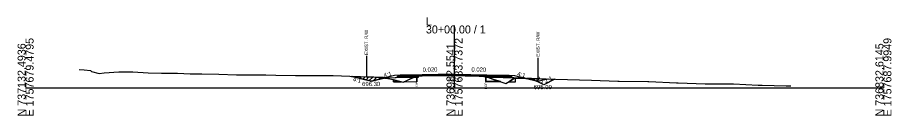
# Model space of a CAD drawing. Extents: x -26 to 4303, y -10 to 9577.
# Drawn here: x 1997.2 to 2302.8, y -9.7 to 24.7 of the extents above; entities that cross this region are included whole.
import ezdxf

# ---------------------------------------------------------------- set-up
doc = ezdxf.new("R2010")
doc.units = 0
for name, color, linetype in [('Default', 7, 'Continuous'), ('Exist CMT Pavement', 7, 'Continuous'), ('Old_Level_10', 7, 'Continuous'), ('Old_Level_2', 7, 'Continuous'), ('Pattern 1', 7, 'Continuous'), ('Prop CMT Conc Surface', 7, 'Continuous'), ('Prop CMT Concrete Structures', 7, 'Continuous'), ('Prop CMT Concrete Wall', 7, 'Continuous'), ('Prop CMT Pvmt Course 1', 7, 'Continuous'), ('Prop CMT Pvmt Course 1 CG', 7, 'Continuous'), ('Prop CMT Pvmt Course 1 Wedge', 7, 'Continuous'), ('Prop CMT Pvmt Course 2', 7, 'Continuous'), ('Prop CMT Pvmt Course 2 Wedge', 7, 'Continuous'), ('Prop CMT Pvmt Course 3', 7, 'Continuous'), ('Prop CMT Pvmt Surface', 7, 'Continuous'), ('Prop CMT Pvmt Surface Shoulder', 7, 'Continuous'), ('Prop CMT Pvmt Wedge Surface 1', 7, 'Continuous'), ('Prop CMT Pvmt Wedge Surface 2', 7, 'Continuous'), ('Prop CMT Pvmt Wedge Surface 3', 7, 'Continuous'), ('Prop CMT Shld Paved Course 1', 7, 'Continuous'), ('Prop CMT Shld Paved Course 2', 7, 'Continuous'), ('Prop CMT Shld Paved Course 3', 7, 'Continuous'), ('Prop CMT Slope Grass', 7, 'Continuous'), ('Prop CMT Subgrade Earthwork', 7, 'Continuous'), ('Prop Road Sect_ Recs - UC Shallow (Outline)', 7, 'Continuous'), ('Prop Shade Light', 7, 'Continuous'), ('Prop XS DDE Elevations', 7, 'Continuous'), ('Prop XS Ditch Standard Text', 7, 'Continuous'), ('Prop XS Earthwork Shape', 7, 'Continuous'), ('Prop XS Hydro Elevations', 7, 'Continuous'), ('Prop XS SE Text', 7, 'Continuous'), ('Prop XS Side Slope Text', 7, 'Continuous'), ('Prop XS Wedging', 7, 'Continuous')]:
    doc.layers.add(name, color=color, linetype=linetype)

msp = doc.modelspace()

# ---------------------------------------------------------------- linework, layer by layer
at = {"layer": 'Exist CMT Pavement'}
for points in [[(2150, 4.84), (2133, 4.5)], [(2150, 4.84), (2167, 4.5)]]:
    msp.add_lwpolyline(points, dxfattribs=at)
at = {"layer": 'Old_Level_10'}
for p, q in [((2176.98, 3.2), (2174.98, 3.3)), ((2181.21, 1.09), (2176.98, 3.2)), ((2185.05, 3.01), (2181.21, 1.09))]:
    msp.add_line(p, q, dxfattribs=at)
at = {"layer": 'Old_Level_2'}
for p, q in [((2150, 0), (2150, 21.86)), ((2150, 0), (2150, 21.86)), ((2000, 0), (2150, 0)), ((2150, 0), (2300, 0)), ((2000, 0), (2150, 0)), ((2150, 0), (2300, 0))]:
    msp.add_line(p, q, dxfattribs=at)
at = {"layer": 'Pattern 1'}
for p, q in [((2114.55, 3.95), (2114.62, 4.02)), ((2115.68, 3.67), (2115.98, 3.96)), ((2116.81, 3.38), (2117.34, 3.91)), ((2117.94, 3.1), (2118.7, 3.86)), ((2119.07, 2.82), (2120.07, 3.81)), ((2120.2, 2.53), (2121.44, 3.77)), ((2121.56, 2.47), (2122.8, 3.72)), ((2123.44, 2.95), (2124.17, 3.67)), ((2125.33, 3.42), (2125.48, 3.57)), ((2160.97, 3.82), (2161.11, 3.96)), ((2175.45, 3.22), (2175.51, 3.29)), ((2176.58, 2.94), (2176.88, 3.24)), ((2177.71, 2.66), (2178.25, 3.2)), ((2178.84, 2.37), (2179.63, 3.16)), ((2180.62, 2.74), (2181, 3.12))]:
    msp.add_line(p, q, dxfattribs=at)
for points in [[(2121, 2.34), (2125.73, 3.52), (2125.21, 3.64), (2121.77, 3.76), (2117.15, 3.92), (2114.21, 4.03)], [(2135.85, 3.72), (2136.77, 4.12), (2136.77, 3.74)], [(2161.61, 3.77), (2160.99, 4.01), (2160.97, 4.01), (2160.97, 3.78)], [(2179, 2.34), (2182.02, 3.09), (2179.71, 3.16), (2176.94, 3.24), (2175.16, 3.3)]]:
    msp.add_lwpolyline(points, close=True, dxfattribs=at)
at = {"layer": 'Prop CMT Conc Surface'}
for points in [[(2136.77, 4.32), (2133, 4.25)], [(2133, 4.25), (2133, 4.04)], [(2133, 4.04), (2136.77, 4.11)], [(2136.77, 4.11), (2136.77, 4.32)], [(2160.97, 4.16), (2160.97, 4.37)], [(2160.97, 4.37), (2167, 4.25)], [(2167, 4.04), (2160.97, 4.16)], [(2167, 4.25), (2167, 4.04)]]:
    msp.add_lwpolyline(points, dxfattribs=at)
at = {"layer": 'Prop CMT Concrete Structures'}
for points in [[(2133, 4.25), (2133, 4.5)], [(2136.77, 4.32), (2133, 4.25)], [(2150, 4.71), (2136.77, 4.45)], [(2136.77, 4.45), (2136.77, 4.32)], [(2150, 4.71), (2160.97, 4.49)], [(2160.97, 4.49), (2160.97, 4.37)], [(2160.97, 4.37), (2167, 4.25)], [(2167, 4.25), (2167, 4.5)]]:
    msp.add_lwpolyline(points, dxfattribs=at)
at = {"layer": 'Prop CMT Pvmt Course 1'}
for points in [[(2136.77, 4.11), (2133, 4.04)], [(2133, 4.04), (2133, 3.71)], [(2133, 3.71), (2136.77, 3.78)], [(2136.77, 3.78), (2136.77, 4.11)], [(2160.97, 4.16), (2167, 4.04)], [(2160.97, 3.83), (2160.97, 4.16)], [(2167, 3.71), (2160.97, 3.83)], [(2167, 4.04), (2167, 3.71)]]:
    msp.add_lwpolyline(points, dxfattribs=at)
at = {"layer": 'Prop CMT Pvmt Course 1 Wedge'}
for points in [[(2147.87, 4.33), (2148.83, 4.35)], [(2150, 4.3), (2149.18, 4.31), (2148.83, 4.32), (2147.87, 4.33)], [(2148.83, 4.35), (2149.18, 4.35), (2150, 4.37)], [(2150, 4.37), (2150, 4.3)], [(2150, 4.37), (2150.55, 4.36), (2150.86, 4.35), (2151.3, 4.34), (2151.3, 4.34), (2153.71, 4.3), (2153.81, 4.29), (2156.14, 4.25), (2156.31, 4.24), (2158.58, 4.2), (2158.81, 4.19), (2159.08, 4.19), (2159.99, 4.17), (2160.2, 4.17), (2160.29, 4.16), (2160.57, 4.16), (2160.61, 4.16), (2160.71, 4.16), (2160.97, 4.15)], [(2160.97, 4.01), (2160.71, 4.02), (2160.61, 4.03), (2160.57, 4.03), (2160.29, 4.04), (2160.2, 4.05), (2159.99, 4.06), (2159.08, 4.09), (2158.81, 4.1), (2158.58, 4.11), (2156.31, 4.17), (2156.14, 4.18), (2153.81, 4.27), (2153.71, 4.27), (2151.3, 4.31), (2151.3, 4.31), (2150.86, 4.3), (2150.55, 4.3), (2150, 4.3)], [(2160.97, 4.15), (2160.97, 4.01)]]:
    msp.add_lwpolyline(points, dxfattribs=at)
at = {"layer": 'Prop CMT Pvmt Course 2'}
for points in [[(2133, 4.5), (2131, 4.46), (2130.74, 4.2)], [(2130.74, 4.2), (2133, 4.25)], [(2133, 4.25), (2133, 4.5)], [(2167, 4.5), (2169, 4.46), (2169.26, 4.2)], [(2167, 4.25), (2167, 4.5)], [(2169.26, 4.2), (2167, 4.25)]]:
    msp.add_lwpolyline(points, dxfattribs=at)
at = {"layer": 'Prop CMT Pvmt Course 2 Wedge'}
for points in [[(2131, 4.46), (2129, 4.3), (2121, 2.3), (2114.02, 4.04)], [(2169, 4.46), (2171, 4.3), (2174.98, 3.3)]]:
    msp.add_lwpolyline(points, dxfattribs=at)
at = {"layer": 'Prop CMT Pvmt Course 3'}
for points in [[(2133, 4.25), (2130.74, 4.2), (2130.53, 3.99)], [(2130.53, 3.99), (2133, 4.04)], [(2133, 4.04), (2133, 4.25)], [(2167, 4.25), (2169.26, 4.2), (2169.47, 3.99)], [(2167, 4.04), (2167, 4.25)], [(2169.47, 3.99), (2167, 4.04)]]:
    msp.add_lwpolyline(points, dxfattribs=at)
at = {"layer": 'Prop CMT Pvmt Surface'}
for points in [[(2150, 4.59), (2133, 4.25)], [(2133, 4.25), (2133, 4.5)], [(2150, 4.59), (2167, 4.25)], [(2167, 4.25), (2167, 4.5)]]:
    msp.add_lwpolyline(points, dxfattribs=at)
at = {"layer": 'Prop CMT Pvmt Surface Shoulder'}
for points in [[(2137.25, 4.33), (2137.57, 4.33), (2137.68, 4.33), (2137.78, 4.33), (2138.08, 4.34), (2138.13, 4.34), (2138.21, 4.35), (2138.36, 4.35), (2138.71, 4.35), (2138.8, 4.35), (2139.12, 4.35), (2141.3, 4.33), (2141.55, 4.33), (2143.8, 4.36), (2146.18, 4.34), (2146.3, 4.34), (2146.36, 4.33), (2147.17, 4.33), (2147.57, 4.32), (2147.82, 4.33), (2148.83, 4.32), (2149.18, 4.31), (2150, 4.3)], [(2150, 4.3), (2150.55, 4.3), (2150.86, 4.3), (2151.3, 4.31), (2151.3, 4.31), (2153.71, 4.27), (2153.81, 4.27), (2156.14, 4.18), (2156.31, 4.17), (2158.58, 4.11), (2158.81, 4.1), (2159.08, 4.09), (2159.99, 4.06), (2160.2, 4.05), (2160.29, 4.04), (2160.57, 4.03), (2160.61, 4.03), (2160.71, 4.02), (2160.97, 4.01)]]:
    msp.add_lwpolyline(points, dxfattribs=at)
at = {"layer": 'Prop CMT Pvmt Wedge Surface 1'}
for p, q in [((2133.02, 3.58), (2125.53, 3.43)), ((2137.25, 3.66), (2133.02, 3.58)), ((2160.97, 3.7), (2166.98, 3.58)), ((2166.98, 3.58), (2174.47, 3.43))]:
    msp.add_line(p, q, dxfattribs=at)
for points in [[(2137.25, 3.66), (2137.25, 4.33)], [(2160.97, 3.7), (2160.97, 4.02)]]:
    msp.add_lwpolyline(points, dxfattribs=at)
at = {"layer": 'Prop CMT Pvmt Wedge Surface 2'}
for points in [[(2136.77, 4.45), (2137.25, 4.46), (2137.57, 4.46), (2137.68, 4.47), (2137.78, 4.47), (2138.08, 4.47), (2138.13, 4.47), (2138.21, 4.48), (2138.36, 4.48), (2138.71, 4.49), (2138.8, 4.49), (2139.12, 4.49), (2141.3, 4.54), (2141.55, 4.54), (2143.8, 4.59), (2146.18, 4.64), (2146.3, 4.64), (2146.36, 4.64), (2147.17, 4.66), (2147.57, 4.66), (2147.82, 4.67), (2148.83, 4.69), (2149.18, 4.7), (2150, 4.71)], [(2150, 4.59), (2149.18, 4.57), (2148.83, 4.56), (2147.82, 4.54), (2147.57, 4.54), (2147.17, 4.53), (2146.36, 4.51), (2146.3, 4.51), (2146.18, 4.51), (2143.8, 4.46), (2141.55, 4.42), (2141.3, 4.41), (2139.12, 4.37), (2138.8, 4.36), (2138.75, 4.36), (2138.71, 4.36), (2138.36, 4.36), (2138.21, 4.35), (2138.16, 4.35), (2138.13, 4.35), (2138.1, 4.35), (2138.08, 4.35), (2137.78, 4.34), (2137.68, 4.34), (2137.57, 4.34), (2137.25, 4.34), (2137.22, 4.33), (2136.77, 4.32)], [(2136.77, 4.32), (2136.77, 4.45)], [(2150, 4.71), (2150, 4.59)], [(2150, 4.71), (2150.55, 4.7), (2150.86, 4.69), (2151.3, 4.69), (2151.3, 4.69), (2153.71, 4.64), (2153.81, 4.64), (2156.14, 4.59), (2156.31, 4.59), (2158.58, 4.54), (2158.81, 4.54), (2159.08, 4.53), (2159.99, 4.51), (2160.2, 4.51), (2160.29, 4.51), (2160.57, 4.5), (2160.61, 4.5), (2160.71, 4.5), (2160.97, 4.49)], [(2160.97, 4.37), (2160.71, 4.37), (2160.61, 4.37), (2160.57, 4.38), (2160.29, 4.38), (2160.2, 4.38), (2159.99, 4.39), (2159.08, 4.41), (2158.81, 4.41), (2158.58, 4.42), (2156.31, 4.46), (2156.14, 4.46), (2153.81, 4.51), (2153.71, 4.51), (2151.3, 4.56), (2151.3, 4.56), (2150.86, 4.57), (2150.55, 4.58), (2150, 4.59)], [(2160.97, 4.49), (2160.97, 4.37)]]:
    msp.add_lwpolyline(points, dxfattribs=at)
at = {"layer": 'Prop CMT Pvmt Wedge Surface 3'}
for points in [[(2136.77, 4.32), (2137.22, 4.33)], [(2137.22, 4.33), (2136.77, 4.13)], [(2136.77, 4.13), (2136.77, 4.32)], [(2138.16, 4.35), (2138.13, 4.35), (2138.1, 4.35)], [(2138.1, 4.35), (2138.13, 4.35)], [(2138.13, 4.35), (2138.16, 4.35)], [(2150, 4.38), (2149.18, 4.36), (2148.83, 4.36), (2147.87, 4.34), (2147.82, 4.34), (2147.57, 4.33), (2147.17, 4.34), (2146.36, 4.34), (2146.3, 4.34), (2146.18, 4.35), (2143.8, 4.37), (2141.55, 4.34), (2141.3, 4.34), (2139.12, 4.36), (2138.8, 4.36), (2138.75, 4.36)], [(2138.75, 4.36), (2138.8, 4.36)], [(2138.8, 4.36), (2139.12, 4.37), (2141.3, 4.41), (2141.55, 4.42), (2143.8, 4.46), (2146.18, 4.51), (2146.3, 4.51), (2146.36, 4.51), (2147.17, 4.53), (2147.57, 4.54), (2147.82, 4.54), (2148.83, 4.56), (2149.18, 4.57), (2150, 4.59)], [(2150, 4.59), (2150, 4.38)], [(2150, 4.59), (2150.55, 4.58), (2150.86, 4.57), (2151.3, 4.56), (2151.3, 4.56), (2153.71, 4.51), (2153.81, 4.51), (2156.14, 4.46), (2156.31, 4.46), (2158.58, 4.42), (2158.81, 4.41), (2159.08, 4.41), (2159.99, 4.39), (2160.2, 4.38), (2160.29, 4.38), (2160.57, 4.38), (2160.61, 4.37), (2160.71, 4.37), (2160.97, 4.37)], [(2160.97, 4.16), (2160.71, 4.16), (2160.61, 4.17), (2160.57, 4.17), (2160.29, 4.17), (2160.2, 4.17), (2159.99, 4.18), (2159.08, 4.2), (2158.81, 4.2), (2158.58, 4.21), (2156.31, 4.25), (2156.14, 4.26), (2153.81, 4.3), (2153.71, 4.3), (2151.3, 4.35), (2151.3, 4.35), (2150.86, 4.36), (2150.55, 4.37), (2150, 4.38)], [(2160.97, 4.37), (2160.97, 4.16)]]:
    msp.add_lwpolyline(points, dxfattribs=at)
at = {"layer": 'Prop CMT Shld Paved Course 1'}
for points in [[(2133, 4.04), (2133, 4.5)], [(2150, 4.38), (2133, 4.04)], [(2150, 4.38), (2167, 4.04)], [(2167, 4.04), (2167, 4.5)]]:
    msp.add_lwpolyline(points, dxfattribs=at)
at = {"layer": 'Prop CMT Shld Paved Course 2'}
for points in [[(2133, 4.5), (2131, 4.46)], [(2167, 4.5), (2169, 4.46)]]:
    msp.add_lwpolyline(points, dxfattribs=at)
at = {"layer": 'Prop CMT Shld Paved Course 3'}
for points in [[(2150, 4.84), (2133, 4.5)], [(2133, 4.5), (2133, 4.25)], [(2133, 4.25), (2136.77, 4.32)], [(2136.77, 4.45), (2150, 4.71)], [(2136.77, 4.32), (2136.77, 4.45)], [(2150, 4.84), (2167, 4.5)], [(2160.97, 4.49), (2150, 4.71)], [(2160.97, 4.37), (2160.97, 4.49)], [(2167, 4.25), (2160.97, 4.37)], [(2167, 4.5), (2167, 4.25)]]:
    msp.add_lwpolyline(points, dxfattribs=at)
at = {"layer": 'Prop CMT Slope Grass'}
msp.add_lwpolyline([(2018.71, 6.4), (2020.43, 6.36), (2022.64, 6.03), (2022.99, 5.75), (2025.7, 5.04), (2027.51, 5.29), (2032.56, 5.64), (2037.51, 5.62), (2042.86, 5.31), (2047.52, 5.17), (2053.15, 5.13), (2057.52, 4.95), (2061.65, 4.95), (2067.53, 4.82), (2073.75, 4.57), (2077.53, 4.51), (2084.05, 4.56), (2087.54, 4.5), (2094.34, 4.39), (2097.55, 4.3), (2104.64, 4.3), (2107.55, 4.31), (2116.25, 3.95), (2125.21, 3.64), (2128.56, 2.88), (2132.07, 1.94), (2134.9, 3.3), (2137.25, 4.33), (2137.78, 4.33), (2138.36, 4.35), (2138.8, 4.35), (2139.12, 4.35), (2141.55, 4.33), (2143.99, 4.36), (2146.36, 4.33), (2147.17, 4.33), (2147.82, 4.33), (2148.83, 4.32), (2149.18, 4.31), (2150, 4.3), (2150.55, 4.3), (2150.86, 4.3), (2151.3, 4.31), (2153.81, 4.27), (2156.31, 4.17), (2159.08, 4.09), (2160.57, 4.03), (2160.99, 4.01), (2163.96, 2.87), (2167.97, 1.57), (2169.98, 2.66), (2170.79, 3.26), (2172.26, 3.39), (2181.17, 3.11), (2197.86, 2.68), (2207.07, 2.33), (2207.62, 2.31), (2217.61, 2.26), (2217.92, 2.26), (2227.61, 1.72), (2228.21, 1.73), (2237.62, 1.46), (2238.51, 1.41), (2247.62, 1.47), (2256.23, 0.99), (2257.63, 0.95), (2265.96, 0.74), (2267.63, 0.71)], dxfattribs=at)
at = {"layer": 'Prop CMT Subgrade Earthwork'}
for points in [[(2133, 4.04), (2130.53, 3.99), (2130.03, 3.98), (2129.69, 3.64)], [(2129.69, 3.64), (2133, 3.71)], [(2133, 3.71), (2133, 4.04)], [(2167, 4.04), (2169.47, 3.99), (2169.97, 3.98), (2170.31, 3.64)], [(2167, 3.71), (2167, 4.04)], [(2170.31, 3.64), (2167, 3.71)]]:
    msp.add_lwpolyline(points, dxfattribs=at)
at = {"layer": 'Prop Road Sect_ Recs - UC Shallow (Outline)'}
for points in [[(2136.77, 2.24), (2136.77, 3.74), (2135.85, 3.72), (2132.51, 2.15)], [(2161.61, 3.77), (2162.8, 3.32), (2163.78, 2.94), (2166.11, 2.18), (2160.97, 2.28), (2160.97, 3.78)], [(2168.98, 2.12), (2171.36, 2.07), (2171.36, 3.31), (2170.79, 3.26), (2169.98, 2.66)], [(2131.36, 2.13), (2128.64, 2.07), (2128.62, 2.86)]]:
    msp.add_lwpolyline(points, close=True, dxfattribs=at)
at = {"layer": 'Prop Shade Light'}
for p, q in [((2134.9, 3.3), (2132.51, 2.15)), ((2136.65, 3.73), (2135.85, 3.72)), ((2136.77, 3.74), (2136.65, 3.73)), ((2136.77, 2.24), (2136.77, 3.74)), ((2160.97, 3.78), (2160.97, 2.28)), ((2161.61, 3.77), (2160.97, 3.78)), ((2163.96, 2.87), (2161.61, 3.77)), ((2170.79, 3.26), (2169.98, 2.66)), ((2171.36, 3.31), (2170.79, 3.26)), ((2171.36, 2.07), (2171.36, 3.31)), ((2128.62, 2.86), (2128.64, 2.07)), ((2131.36, 2.13), (2128.62, 2.86)), ((2128.64, 2.07), (2131.36, 2.13)), ((2132.51, 2.15), (2136.77, 2.24)), ((2160.97, 2.28), (2166.11, 2.18)), ((2166.11, 2.18), (2163.96, 2.87)), ((2169.98, 2.66), (2168.98, 2.12)), ((2168.98, 2.12), (2171.36, 2.07))]:
    msp.add_line(p, q, dxfattribs=at)
msp.add_lwpolyline([(2135.85, 3.72), (2135.85, 3.72), (2134.9, 3.3)], dxfattribs=at)
at = {"layer": 'Prop XS DDE Elevations'}
for points in [[(2114.02, 4.04), (2116.25, 3.95), (2125.21, 3.64), (2125.81, 3.5), (2125.53, 3.43), (2121, 2.3)], [(2125.81, 3.5), (2125.53, 3.43), (2126.07, 3.44)], [(2126.07, 3.44), (2128.56, 2.88), (2132.07, 1.94), (2134.9, 3.3), (2135.66, 3.63), (2133.02, 3.58)], [(2135.66, 3.63), (2137.25, 4.33), (2137.25, 3.66)], [(2137.25, 4.33), (2137.78, 4.33), (2137.68, 4.33), (2137.57, 4.33)], [(2138.08, 4.34), (2138.13, 4.34), (2138.19, 4.34)], [(2138.21, 4.35), (2138.36, 4.35), (2138.19, 4.34)], [(2138.36, 4.35), (2138.8, 4.35), (2138.71, 4.35)], [(2139.12, 4.35), (2141.55, 4.33), (2141.3, 4.33)], [(2141.55, 4.33), (2143.8, 4.36), (2143.99, 4.36)], [(2147.57, 4.32), (2147.82, 4.33), (2147.17, 4.33)], [(2153.81, 4.27), (2156.31, 4.17), (2156.14, 4.18)], [(2158.81, 4.1), (2159.08, 4.09), (2156.31, 4.17), (2158.58, 4.11)], [(2160.2, 4.05), (2160.29, 4.04), (2160.57, 4.03), (2159.08, 4.09), (2159.99, 4.06)], [(2160.62, 4.03), (2160.71, 4.02), (2160.97, 4.02)], [(2160.99, 4.01), (2161.84, 3.68), (2160.97, 3.7), (2160.97, 4.02)], [(2163.96, 2.87), (2167.97, 1.57), (2169.98, 2.66), (2170.79, 3.26), (2172.26, 3.39), (2174.98, 3.3), (2174.47, 3.43), (2166.98, 3.58), (2161.84, 3.68)]]:
    msp.add_lwpolyline(points, close=True, dxfattribs=at)
at = {"layer": 'Prop XS Ditch Standard Text'}
for p, q in [((2119.2, 11.25), (2119.2, 3.84)), ((2179.2, 10.57), (2179.2, 3.17)), ((2136.77, 4.12), (2136.77, 2.07)), ((2160.97, 4.01), (2160.97, 1.96))]:
    msp.add_line(p, q, dxfattribs=at)
at = {"layer": 'Prop XS Earthwork Shape'}
msp.add_lwpolyline([(2185.05, 3.01), (2181.21, 1.09), (2176.98, 3.2), (2174.94, 3.3), (2181.17, 3.11)], close=True, dxfattribs=at)
at = {"layer": 'Prop XS Wedging'}
for p, q in [((2150, 4.71), (2137.25, 4.46)), ((2137.25, 4.34), (2137.25, 4.48)), ((2137.25, 4.46), (2137.25, 4.34)), ((2137.25, 4.34), (2137.25, 4.33)), ((2147.73, 4.54), (2147.52, 4.33)), ((2147.52, 4.33), (2147.73, 4.54)), ((2147.73, 4.54), (2147.52, 4.33)), ((2147.73, 4.54), (2150, 4.59)), ((2147.73, 4.54), (2150, 4.59)), ((2160.97, 4.49), (2150, 4.71)), ((2160.97, 4.37), (2150, 4.59)), ((2150, 4.59), (2150, 4.59)), ((2150, 4.59), (2150, 4.59)), ((2150, 4.59), (2160.97, 4.37)), ((2160.97, 4.37), (2160.97, 4.49)), ((2160.97, 4.16), (2160.97, 4.37)), ((2160.97, 4.02), (2160.97, 4.16)), ((2160.97, 4.01), (2160.97, 4.02))]:
    msp.add_line(p, q, dxfattribs=at)
for points in [[(2137.25, 4.33), (2137.78, 4.33), (2138.36, 4.35), (2138.8, 4.35), (2139.12, 4.35), (2141.55, 4.33), (2143.99, 4.36), (2146.36, 4.33), (2147.17, 4.33), (2147.52, 4.33)], [(2147.52, 4.33), (2147.52, 4.33)], [(2147.52, 4.33), (2147.52, 4.33)], [(2147.52, 4.33), (2147.82, 4.33), (2148.83, 4.32), (2149.18, 4.31), (2150, 4.3), (2150.55, 4.3), (2150.86, 4.3), (2151.3, 4.31), (2153.81, 4.27), (2156.31, 4.17), (2159.08, 4.09), (2160.57, 4.03), (2160.97, 4.01)], [(2150, 4.59), (2150, 4.59), (2147.73, 4.54)], [(2150, 4.59), (2150, 4.59)], [(2150, 4.59), (2150, 4.59)], [(2160.97, 4.37), (2150, 4.59), (2150, 4.59)], [(2160.97, 4.02), (2160.97, 4.02)]]:
    msp.add_lwpolyline(points, dxfattribs=at)

# ---------------------------------------------------------------- texts
at = {"layer": 'Default'}
msp.add_text('-', height=0.0001, dxfattribs=at).set_placement((2000, 0))
at = {"layer": 'Old_Level_2'}
for s, p in [('L', (2140, 21.86)), ('L', (2140, 21.86)), ('30+00.00 / 1', (2140, 19.06)), ('30+00.00 / 1', (2140, 19.06))]:
    msp.add_text(s, height=2.8, dxfattribs=at).set_placement(p)
for s, p in [('N 737132.4936', (2000, -10)), ('N 737132.4936', (2000, -10)), ('E 1757679.4795', (2002.8, -10)), ('E 1757679.4795', (2002.8, -10)), ('N 736982.5541', (2150, -10)), ('N 736982.5541', (2150, -10)), ('E 1757683.7372', (2152.8, -10)), ('E 1757683.7372', (2152.8, -10)), ('N 736832.6145', (2300, -10)), ('N 736832.6145', (2300, -10)), ('E 1757687.9949', (2302.8, -10)), ('E 1757687.9949', (2302.8, -10))]:
    msp.add_text(s, height=2.8, rotation=90, dxfattribs=at).set_placement(p)
at = {"layer": 'Prop CMT Concrete Wall'}
for rotation, p in [(334.1383, (2178.43, 2.75)), (25.8617, (2181.86, 1.67))]:
    msp.add_text('2:1', height=1.5, rotation=rotation, dxfattribs=at).set_placement(p)
msp.add_text('695.09', height=1.5, dxfattribs=at).set_placement((2177.72, -0.46))
at = {"layer": 'Prop CMT Pvmt Course 1 CG'}
msp.add_text('698.30', height=1, dxfattribs=at).set_placement((2147.85, 2.3))
at = {"layer": 'Prop XS Ditch Standard Text'}
for s, height, p in [('EXIST. R/W', 1.181, (2119.79, 11.55)), ('EXIST. R/W', 1.181, (2179.79, 10.87)), ('EOP', 0.787, (2137.16, -0.33)), ('EOP', 0.787, (2161.37, -0.44))]:
    msp.add_text(s, height=height, rotation=90, dxfattribs=at).set_placement(p)
at = {"layer": 'Prop XS Hydro Elevations'}
msp.add_text('696.30', height=1.5, dxfattribs=at).set_placement((2117.69, 0.62))
at = {"layer": 'Prop XS SE Text'}
for rotation, p in [(1.1458, (2138.86, 5.61)), (358.8542, (2155.9, 5.72))]:
    msp.add_text('0.020', height=1.5, rotation=rotation, dxfattribs=at).set_placement(p)
at = {"layer": 'Prop XS Side Slope Text'}
for rotation, p in [(345.9638, (2114.34, 2.35)), (14.0362, (2125.37, 3.6)), (345.9638, (2171.85, 4.26))]:
    msp.add_text('4:1', height=1.5, rotation=rotation, dxfattribs=at).set_placement(p)

doc.saveas('drawing.dxf')
